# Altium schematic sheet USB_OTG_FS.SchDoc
size A4; DocumentNumber: 5; Revision: B.2(PCB.SCH); SheetNumber: 5; SheetTotal: 6
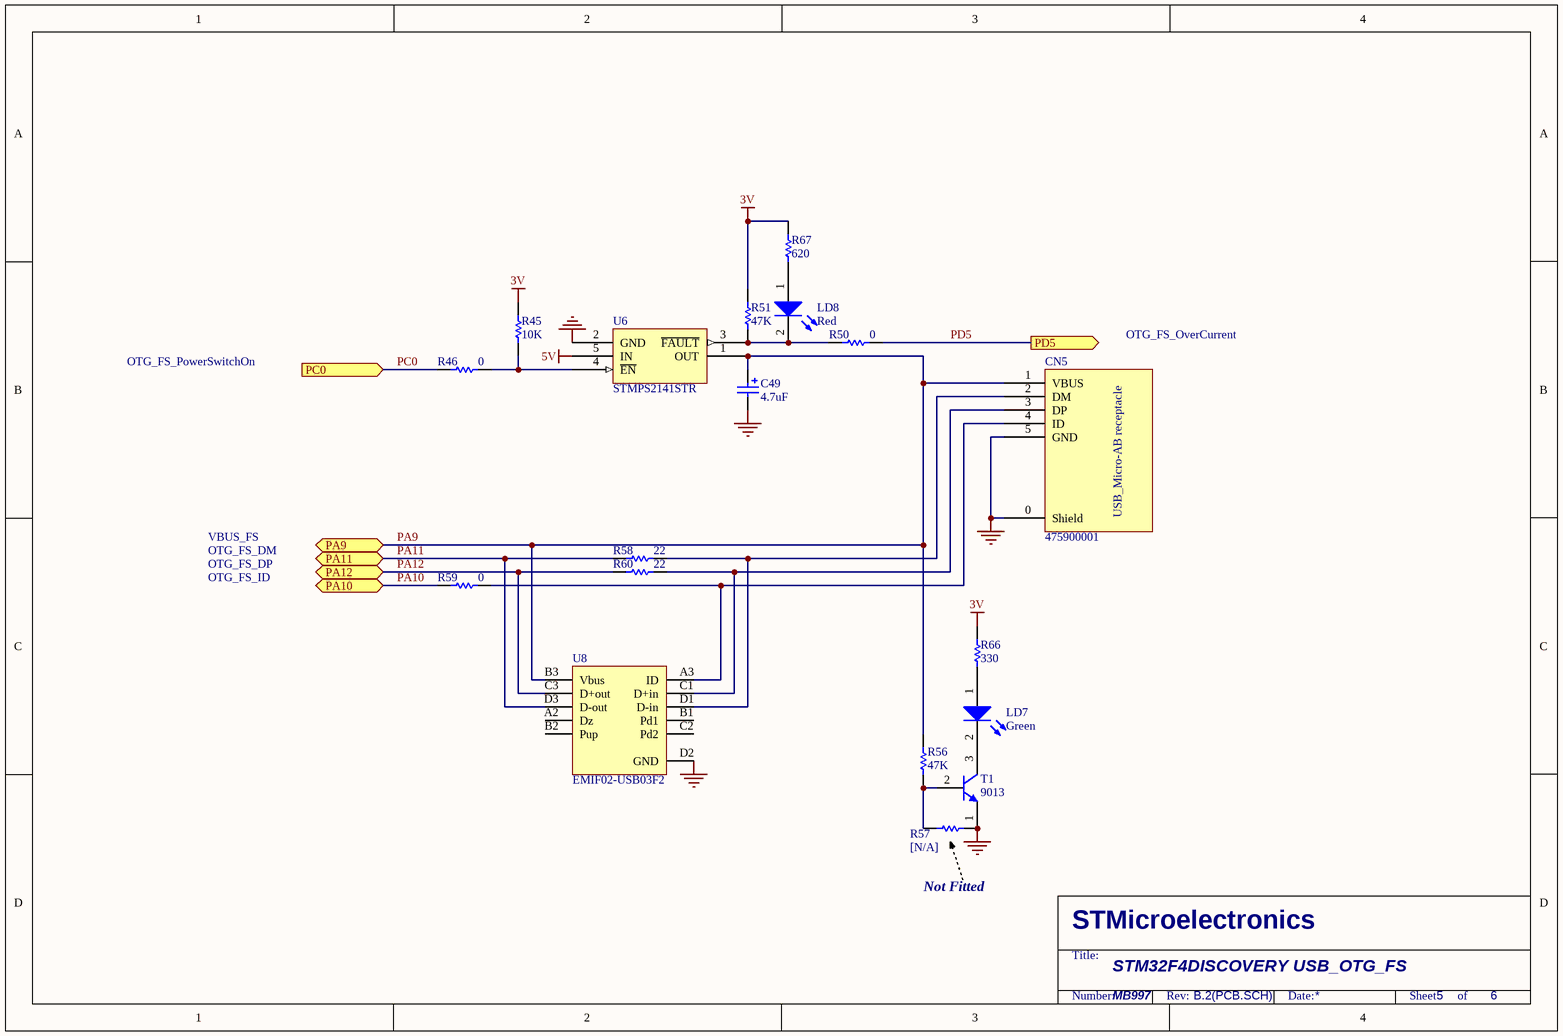
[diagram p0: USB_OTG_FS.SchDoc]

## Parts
C49  4.7uF  [TAN-A]
CN5  475900001  [USB-MICRO-AB]
LD7  Green  [0603D]
LD8  Red  [0603D]
R45  10K  [0402R]
R46  0  [0603R]
R50  0  [0603R]
R51  47K  [0402R]
R56  47K  [0402R]
R57  [N/A]  [0603R]
R58  22  [0603R]
R59  0  [0603R]
R60  22  [0603R]
R66  330  [0603R]
R67  620  [0603R]
T1  9013  [SOT-23]
U6  STMPS2141STR  [SOT23-5L]
U8  EMIF02-USB03F2  [Flip Chip]

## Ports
PA9 (bidir), PA10 (bidir), PA11 (bidir), PA12 (bidir), PC0 (in), PD5 (out)

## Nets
3V: R45.1 R51.1 R66.2 R67.2
5V: U6.5(IN)
GND: C49.2 CN5.0(Shield) CN5.5(GND) R57.1 T1.1(E) U6.2(GND) U8.D2(GND)
PA9: C49.1 CN5.1(VBUS) R56.2 U6.1(OUT) U8.B3(Vbus) ; port PA9
PA10: R59.2 ; port PA10
PA11: R58.2 U8.D3(D-out) ; port PA11
PA12: R60.2 U8.C3(D+out) ; port PA12
PC0: R46.2 ; port PC0
PD5: R50.1 ; port PD5
NetCN5_2: CN5.2(DM) R58.1 U8.D1(D-in)
NetCN5_3: CN5.3(DP) R60.1 U8.C1(D+in)
NetCN5_4: CN5.4(ID) R59.1 U8.A3(ID)
NetLD7_1: LD7.1(A) R66.1
NetLD7_2: LD7.2(K) T1.3(C)
NetLD8_1: LD8.1(A) R67.1
NetLD8_2: LD8.2(K) R50.2 R51.2 U6.3(~{FAULT})
NetR45_2: R45.2 R46.1 U6.4(~{EN})
NetR56_1: R56.1 R57.2 T1.2(B)

Not connected (* = marked no-connect by the designer): U8 A2(Dz) B1(Pd1) B2(Pup) C2(Pd2)

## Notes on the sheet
- OTG_FS_PowerSwitchOn
- OTG_FS_OverCurrent
- VBUS_FS
- OTG_FS_ID
- OTG_FS_DM
- OTG_FS_DP
- Not Fitted
- STM32F4DISCOVERY USB_OTG_FS
- MB997

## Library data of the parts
C49 = Cap Pol1: Polarized Capacitor (Radial); Value: 47uF
LD7 LD8 = LED2: Typical RED, GREEN, YELLOW, AMBER GaAs LED
R45 R51 R56 R66 = res1: Resistor; Value: 1K
R46 R50 R58-R60 R67 = Res1: Resistor; Value: 1K
R57 = res1: Resistor; Value: 1K; Fitted: NO
T1 = NPN: NPN Bipolar Transistor; Code - JEDEC: TO-226-AA
U6 = STMPS2141STR: Enhanced single channel power switches; Manuf_1: STM; Provided: ST
U8 = EMIF02-USB03F2: 2-line IPAD, EMI filter including ESD protection; Manuf_1: STM; Provided: ST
